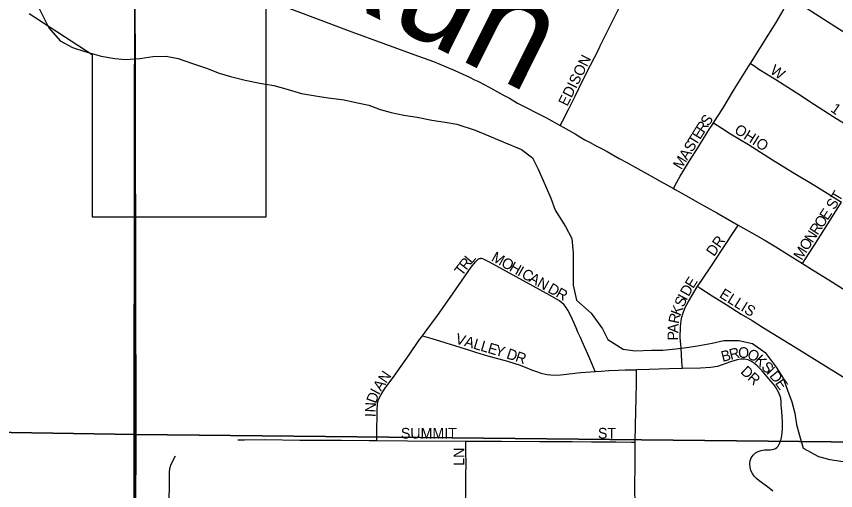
# Model space of a CAD drawing. Extents: x 1874609 to 2204689, y 815661 to 1281160.
# Drawn here: x 2012353 to 2016212, y 1046249 to 1048482 of the extents above; entities that cross this region are included whole.
import ezdxf

# ---------------------------------------------------------------- set-up
doc = ezdxf.new("R2010")
doc.units = 0
for name, color, linetype in [('GM_X_City_Street', 7, 'Continuous'), ('GM_X_City_Street_Text', 7, 'Continuous'), ('GM_X_Corporation', 7, 'Continuous'), ('GM_X_Minor_River', 7, 'Continuous'), ('GM_X_Minor_River_Text', 7, 'Continuous'), ('GM_X_Section', 7, 'Continuous'), ('GM_X_State_Route', 7, 'Continuous'), ('GM_X_Township', 7, 'Continuous')]:
    doc.layers.add(name, color=color, linetype=linetype)

msp = doc.modelspace()

# ---------------------------------------------------------------- linework, layer by layer
at = {"layer": 'GM_X_City_Street'}
for points in [[(2015811.1, 1048260), (2015870.7, 1048355.6), (2015932.6, 1048452.6), (2015964.4, 1048510), (2015971.6, 1048524.4), (2015977.6, 1048539.3), (2015982.3, 1048554.6), (2015986.1, 1048571.6)], [(2015986.1, 1048571.6), (2015992.4, 1048568.6), (2016077.8, 1048518.7), (2016230.2, 1048421.2), (2016352.6, 1048344.8)], [(2014914, 1047967.7), (2014924.9, 1047988.5), (2014955.3, 1048046.6), (2014984.5, 1048105.2), (2015020.1, 1048178.4), (2015057.2, 1048251.2), (2015094.4, 1048324), (2015103.4, 1048342.3), (2015180.9, 1048500.4), (2015196.5, 1048531.8)], [(2015636.4, 1047979.8), (2015680, 1048047.7), (2015731.7, 1048131.9), (2015809.7, 1048257.8), (2015811.1, 1048260)], [(2015811.1, 1048260), (2015826.5, 1048249.8), (2015851, 1048233.5), (2015886.6, 1048211.2), (2015929.6, 1048184.5), (2015969, 1048159.3), (2016038, 1048115.5), (2016112.2, 1048067.2), (2016200.3, 1048010.5), (2016254, 1047977.4), (2016311.9, 1047942), (2016378.6, 1047899.4), (2016410.1, 1047879.7)], [(2015448.1, 1047671.5), (2015464.2, 1047700.6), (2015480.3, 1047729.5), (2015531.9, 1047813.6), (2015557.8, 1047855.3), (2015601.1, 1047923.8), (2015617.8, 1047951.6), (2015627.1, 1047965.3), (2015636.4, 1047979.8)], [(2015636.4, 1047979.8), (2015676, 1047955), (2015717.4, 1047929.1), (2015801, 1047878.1), (2015914, 1047806.8), (2016008.4, 1047748.8), (2016121.6, 1047680), (2016240.5, 1047606.5)], [(2016056, 1047317.5), (2016067, 1047334.7), (2016110.2, 1047402.3), (2016159.6, 1047479.8), (2016240.5, 1047606.5)], [(2015560.9, 1047209.9), (2015623.6, 1047302.9), (2015677.9, 1047384.4), (2015744.9, 1047486), (2015753.2, 1047498.7)], [(2014265.4, 1046977.4), (2014278.1, 1046994.8), (2014336.1, 1047073.6), (2014374.2, 1047126.8), (2014421.1, 1047193.8), (2014495.8, 1047300.2), (2014515.7, 1047325.2), (2014521.5, 1047332.3), (2014526.4, 1047337.6), (2014530.1, 1047340.4), (2014534.5, 1047342.2), (2014539.7, 1047342.2)], [(2015078.9, 1046809.9), (2015063.3, 1046847.4), (2015044.9, 1046891.8), (2015018.2, 1046951), (2015009.8, 1046970.3), (2014998.1, 1046995.1), (2014989.4, 1047014.7), (2014972, 1047054.4), (2014958.2, 1047083.5), (2014950.8, 1047097.6), (2014942.5, 1047110.9), (2014932.6, 1047122.9), (2014921.3, 1047133.6), (2014908.7, 1047143.1), (2014866.9, 1047167.6), (2014738.8, 1047238.7), (2014581.4, 1047324.2), (2014563.1, 1047334.2), (2014549.8, 1047340.4), (2014544.3, 1047341.7), (2014539.7, 1047342.2)], [(2015490.4, 1046822.9), (2015488.2, 1046856.2), (2015484, 1046921.1), (2015481, 1046952.9), (2015480.4, 1046969), (2015481.4, 1047017.5), (2015484.9, 1047049.3), (2015488.2, 1047064.9), (2015492.4, 1047080.3), (2015503.8, 1047110.2), (2015518.3, 1047138.8), (2015559.9, 1047208.4), (2015560.9, 1047209.9)], [(2015560.9, 1047209.9), (2015571.9, 1047202.9), (2015630.5, 1047165.2), (2015696.9, 1047124.3), (2015767.7, 1047080), (2015818.6, 1047049.1), (2015866.8, 1047019), (2015964.8, 1046958.4), (2016020.7, 1046923.7), (2016132.2, 1046854.6), (2016244.2, 1046785.5), (2016385, 1046700), (2016441.2, 1046666.2), (2016466.1, 1046650.2), (2016488.4, 1046635.1), (2016536.8, 1046600.8), (2016599.7, 1046553.8), (2016643.8, 1046520.9), (2016680.8, 1046493), (2016701.2, 1046477.7)], [(2014050.8, 1046484.2), (2014051, 1046501.2), (2014051.5, 1046560.5), (2014051.7, 1046579), (2014052.1, 1046625.7), (2014054.5, 1046658), (2014057.7, 1046673.2), (2014063.3, 1046687.7), (2014070.8, 1046701.7), (2014088.8, 1046728.7), (2014127.1, 1046781.5), (2014202.6, 1046888.3), (2014249.3, 1046955.2), (2014265.4, 1046977.4)], [(2014265.4, 1046977.4), (2014309.6, 1046964.1), (2014325.4, 1046959.4), (2014371.6, 1046945.3), (2014401.7, 1046936.1), (2014416.7, 1046931.3), (2014446.8, 1046922.1), (2014483.3, 1046910.8), (2014516.1, 1046900.5), (2014556.4, 1046888.3), (2014613.6, 1046872.4), (2014655.7, 1046861.2), (2014691.4, 1046850.4), (2014706.1, 1046845.3), (2014720.8, 1046840.1), (2014749.7, 1046829.2), (2014778.6, 1046818.1), (2014808, 1046807.4), (2014823.1, 1046802.3), (2014838.4, 1046797.9), (2014853.9, 1046794.7), (2014869.1, 1046793.1), (2014899.8, 1046792.9), (2014931.4, 1046795.2), (2014995.3, 1046803.5), (2015011.5, 1046804.6), (2015078.9, 1046809.9)], [(2015916.2, 1046245.4), (2015891, 1046266.9), (2015851.2, 1046295), (2015839.1, 1046305.3), (2015828.5, 1046317), (2015819.7, 1046329.9), (2015812.9, 1046344), (2015808.7, 1046358.9), (2015807.4, 1046374.1), (2015809.4, 1046389.1), (2015814.7, 1046403.2), (2015823.2, 1046415.7), (2015834.3, 1046425.8), (2015847.5, 1046433.2), (2015862, 1046437.9), (2015877.5, 1046440), (2015893.7, 1046440.8), (2015904.2, 1046441.3), (2015912.4, 1046442.3), (2015921.1, 1046444.5), (2015928.8, 1046447.5), (2015935.7, 1046452.3), (2015941.4, 1046458.6), (2015946, 1046467.6), (2015949.1, 1046473.7), (2015952.8, 1046483.9), (2015954.9, 1046491.1), (2015958.4, 1046506.5), (2015960.6, 1046523), (2015961.9, 1046539.5), (2015962.3, 1046556.1), (2015961.8, 1046572.5), (2015958, 1046620.7), (2015956.8, 1046635.6), (2015955.8, 1046650.9), (2015955.4, 1046667.3), (2015953.7, 1046684.6), (2015947.6, 1046701.1), (2015940.6, 1046714.6), (2015934.9, 1046725.8), (2015928.1, 1046737.1), (2015919.1, 1046749.4), (2015908.8, 1046762.2), (2015897.8, 1046775.1), (2015865.3, 1046812.3), (2015842, 1046836.1), (2015829.2, 1046847.1), (2015815.1, 1046856.8), (2015799.3, 1046863.9), (2015782.5, 1046867.5), (2015765.3, 1046867.3), (2015748.5, 1046864.5), (2015716.3, 1046855.7), (2015655, 1046833.3), (2015623.4, 1046827.8), (2015574.9, 1046824.4), (2015490.4, 1046822.9)], [(2015078.9, 1046809.9), (2015107, 1046811.5), (2015144.1, 1046813.4), (2015188.2, 1046816.3), (2015220.5, 1046817), (2015274.5, 1046817.7)], [(2015268, 1046477), (2015269.3, 1046556.2), (2015273.2, 1046686.2), (2015274.3, 1046754.4), (2015274.5, 1046817.7)], [(2015490.4, 1046822.9), (2015427.3, 1046821.9), (2015333.2, 1046818.6), (2015274.5, 1046817.7)], [(2013396.1, 1046488), (2013427, 1046488.3), (2013523.7, 1046488.7), (2013687.5, 1046486.5), (2013785.7, 1046486), (2013883.7, 1046485.8), (2014014.7, 1046484.6), (2014050.8, 1046484.2)], [(2014050.8, 1046484.2), (2014195.1, 1046482.6), (2014469.9, 1046481.1)], [(2014467, 1046133.5), (2014468, 1046182.8), (2014470.4, 1046248.3), (2014470.7, 1046330.4), (2014471.3, 1046363.2), (2014470.3, 1046444.9), (2014469.9, 1046481.1)], [(2014469.9, 1046481.1), (2014472.7, 1046481.1), (2014637.7, 1046481.2), (2014817.3, 1046479.8), (2014901.7, 1046480.1), (2014971, 1046479.1), (2015062, 1046478.3), (2015176.3, 1046477.9), (2015251.1, 1046477.2), (2015268, 1046477)], [(2015267, 1046113.2), (2015267.1, 1046181), (2015266.6, 1046262.6), (2015267.1, 1046376.9), (2015267.9, 1046474.8), (2015268, 1046477)], [(2013073.1, 1046143.1), (2013073.4, 1046335.8), (2013076.1, 1046352), (2013080.2, 1046367.8), (2013086.5, 1046383), (2013102.3, 1046411.9)]]:
    msp.add_lwpolyline(points, dxfattribs=at)
at = {"layer": 'GM_X_Corporation'}
msp.add_lwpolyline([(2012412.4, 1048494.5), (2012709.9, 1048301.4), (2012709.8, 1047537.4), (2013530.1, 1047537.4), (2013530.1, 1048534.6)], dxfattribs=at)
at = {"layer": 'GM_X_Minor_River'}
for points in [[(2012453.3, 1048531), (2012506.3, 1048427), (2012559, 1048367.2), (2012617.4, 1048335.5), (2012675.7, 1048315.8), (2012752.1, 1048294.3), (2012816.4, 1048282.8), (2012866.6, 1048279.1), (2012934.7, 1048283.6), (2012994.8, 1048292.1), (2013059, 1048294.6), (2013115.3, 1048283), (2013181.7, 1048259.4), (2013248, 1048237.8), (2013308.4, 1048214.1), (2013360.7, 1048198.5), (2013431, 1048180.9), (2013499.4, 1048167.4), (2013565.6, 1048155.8), (2013621.9, 1048140.2), (2013696.3, 1048118.7), (2013770.7, 1048105.2), (2013820.9, 1048097.5), (2013897.2, 1048088), (2013959.5, 1048074.5), (2014013.7, 1048062.8), (2014066, 1048043.1), (2014118.3, 1048029.5), (2014178.6, 1048015.9), (2014240.8, 1048006.3), (2014309.2, 1047992.8), (2014373.4, 1047983.2), (2014427.7, 1047973.5), (2014514.1, 1047946.1), (2014578.6, 1047918.5), (2014649, 1047888.9), (2014731.5, 1047855.4), (2014784, 1047815.6), (2014810.5, 1047761.6), (2014835, 1047709.6), (2014869.8, 1047625.6), (2014890.4, 1047569.5), (2014939.1, 1047491.6), (2014969.7, 1047435.6)], [(2014969.7, 1047435.6), (2014976.3, 1047367.4)], [(2014976.3, 1047367.4), (2014976, 1047216.3), (2014991.3, 1047144.9), (2015061.2, 1047084.4), (2015113.1, 1047010), (2015139, 1046959.7), (2015211, 1046915.2), (2015267.1, 1046907), (2015345.3, 1046910.6), (2015397.4, 1046910.4), (2015459.6, 1046916.1), (2015509.7, 1046921.9), (2015561.9, 1046929.7), (2015630.1, 1046943.5), (2015686.2, 1046955.3), (2015756.4, 1046954.9), (2015820.5, 1046940.6), (2015880.5, 1046898.2), (2015932.4, 1046829.8), (2015964.2, 1046777.5), (2015986.1, 1046721.2), (2016006, 1046666.9), (2016019.8, 1046612.7), (2016027.6, 1046560.5), (2016041.5, 1046508.3), (2016059.3, 1046448), (2016131.3, 1046409.6), (2016185.4, 1046395.3), (2016247.5, 1046385)]]:
    msp.add_lwpolyline(points, dxfattribs=at)
at = {"layer": 'GM_X_Section'}
for points in [[(2012905.1, 1051801), (2012915.3, 1046513.3), (2007626.4, 1046598.1), (2007622.1, 1051897.9)], [(2019058.5, 1051739.8), (2019020.7, 1046448.2), (2012915.3, 1046513.3), (2012905.1, 1051801)], [(2012915.3, 1046513.3), (2012892.7, 1041156.5), (2007599.8, 1041247.3), (2007626.4, 1046598.1)], [(2019020.7, 1046448.2), (2018988, 1041097.3), (2012892.7, 1041156.5), (2012915.3, 1046513.3)]]:
    msp.add_lwpolyline(points, close=True, dxfattribs=at)
at = {"layer": 'GM_X_State_Route'}
for points in [[(2013581, 1048540.8), (2013703.1, 1048495.1), (2013737, 1048482.5), (2013933.2, 1048409.3), (2014225.4, 1048302.8), (2014317.2, 1048268.7), (2014407.8, 1048231.2), (2014418.4, 1048226.3)], [(2014418.4, 1048226.3), (2014452.4, 1048210.6), (2014486.9, 1048195.5), (2014511.3, 1048183.6), (2014525.8, 1048176.4), (2014559, 1048159), (2014594.4, 1048140.1), (2014619.9, 1048126.8), (2014647.6, 1048110.2), (2014675.3, 1048095.8), (2014714.1, 1048073.6), (2014847.2, 1048004.9), (2014914, 1047967.7), (2014956.9, 1047943.9), (2014984.6, 1047928.4), (2015007.8, 1047914), (2015031.1, 1047900.7), (2015055.5, 1047887.4), (2015081, 1047874.1), (2015108.7, 1047859.6), (2015135.3, 1047845.2), (2015162.8, 1047829.6), (2015191.9, 1047813.1), (2015228.4, 1047793.1), (2015267.2, 1047771), (2015323.8, 1047739.9), (2015385.8, 1047705.5), (2015448.1, 1047671.5), (2015456.8, 1047666.8), (2015497.8, 1047643.5), (2015562.1, 1047606.9), (2015651.8, 1047555.9), (2015722.8, 1047516), (2015753.2, 1047498.7), (2015818.1, 1047461.7), (2015874.7, 1047430), (2015930.4, 1047396), (2015985.8, 1047361.3), (2016056, 1047317.5), (2016110.7, 1047283.3), (2016179.7, 1047241.1), (2016262.2, 1047189)]]:
    msp.add_lwpolyline(points, dxfattribs=at)
at = {"layer": 'GM_X_Township'}
for points in [[(2012924.9, 1056002.2), (2012935.3, 1053679.3), (2012914.5, 1051827.7), (2012910.2, 1048822.6), (2012903.7, 1044302.1), (2012899.1, 1041173.4), (2012896.1, 1039044.8), (2012861.2, 1035880.2), (2012864.4, 1032937.1), (2012859.2, 1032479.4), (2012845.9, 1030538.4), (2012837.6, 1027645.9), (2012830.6, 1025241.9), (2010175.8, 1025275.6)], [(2037504.4, 1025002.2), (2030477.9, 1025070.5), (2023338.3, 1025139.8), (2019554.9, 1025176.6), (2018880.2, 1025183.1), (2014559, 1025225.1), (2013359, 1025236.7), (2012830.6, 1025241.9), (2012837.6, 1027645.9), (2012845.9, 1030538.4), (2012859.2, 1032479.4), (2012864.4, 1032937.1), (2012861.2, 1035880.2), (2012896.1, 1039044.8), (2012899.1, 1041173.4), (2012903.7, 1044302.1), (2012910.2, 1048822.6), (2012914.5, 1051827.7), (2012935.3, 1053679.3), (2012924.9, 1056002.2)]]:
    msp.add_lwpolyline(points, dxfattribs=at)

# ---------------------------------------------------------------- texts
at = {"layer": 'GM_X_City_Street_Text'}
for s, rotation, p in [('EDISON', 63.4349, (2014947.5, 1048055.1)), ('W', 326.0162, (2015899.3, 1048216.4)), ('1', 324.8724, (2016184.6, 1048036.6)), ('S', 55.6659, (2015612.8, 1047961.3)), ('R', 57.2867, (2015591.7, 1047928.3)), ('E', 58.0989, (2015573.2, 1047898.6)), ('OHIO', 327.6586, (2015731, 1047935.6)), ('T', 58.0989, (2015554.6, 1047868.7)), ('S', 58.1095, (2015536, 1047838.9)), ('M', 58.0834, (2015484.8, 1047756.7)), ('A', 58.0908, (2015512.7, 1047801.5)), ('ST', 59.0277, (2016206.3, 1047567.4)), ('E', 56.3071, (2016173.4, 1047518.1)), ('O', 56.3099, (2016149, 1047481.5)), ('N', 56.6252, (2016102.9, 1047411.8)), ('R', 56.3234, (2016127.1, 1047448.5)), ('DR', 54.7814, (2015639, 1047347.8)), ('O', 58.1104, (2016079.8, 1047374.8)), ('M', 58.5333, (2016052.3, 1047329.8)), ('M', 330.8357, (2014586.5, 1047333.1)), ('R', 52.2388, (2014472.9, 1047283.5)), ('L', 49.6032, (2014496.8, 1047314.3)), ('O', 330.8244, (2014632.7, 1047307.4)), ('H', 330.8267, (2014671.1, 1047285.9)), ('T', 52.2448, (2014451.4, 1047255.6)), ('I', 330.8137, (2014709.5, 1047264.5)), ('C', 330.8422, (2014728.7, 1047253.8)), ('A', 330.8244, (2014763.3, 1047234.5)), ('N', 330.8267, (2014801.7, 1047213)), ('E', 57.9541, (2015540.8, 1047197.1)), ('D', 330.8244, (2014851.7, 1047185.1)), ('R', 331.0174, (2014890.2, 1047163.6)), ('D', 60.6482, (2015519.6, 1047159.3)), ('I', 62.4573, (2015509.6, 1047140.2)), ('ELLIS', 327.9952, (2015660.5, 1047161.3)), ('S', 65.8794, (2015495.6, 1047108.8)), ('K', 68.5639, (2015479.7, 1047068.4)), ('R', 78.0613, (2015472.2, 1047031.7)), ('A', 87.3111, (2015470.4, 1046989.9)), ('V', 343.7634, (2014417.4, 1046942.3)), ('A', 343.7882, (2014459.7, 1046930)), ('P', 89.6175, (2015470.1, 1046955.2)), ('L', 343.7769, (2014501.9, 1046917.7)), ('L', 343.7612, (2014535.7, 1046907.9)), ('E', 343.7845, (2014569.5, 1046898)), ('Y', 343.7153, (2014603.3, 1046888.2)), ('D', 341.9797, (2014657.8, 1046872.1)), ('R', 341.5651, (2014699.5, 1046858.6)), ('B', 14.3838, (2015679.4, 1046854.4)), ('R', 14.3765, (2015717.8, 1046864.2)), ('O', 0.4809, (2015753, 1046873.6)), ('O', 333.3665, (2015790.9, 1046875.4)), ('K', 315.6337, (2015826.9, 1046858)), ('D', 316.5766, (2015760.7, 1046804.7)), ('S', 314.5942, (2015858.2, 1046827.4)), ('I', 314.5674, (2015882.9, 1046802.4)), ('N', 56.2311, (2014094.8, 1046750.6)), ('R', 317.656, (2015793.4, 1046773.8)), ('D', 309.5201, (2015897.6, 1046787.6)), ('E', 304.8645, (2015924.9, 1046754.5)), ('A', 56.6252, (2014070.7, 1046713.9)), ('D', 70.1551, (2014046.6, 1046656)), ('I', 61.3826, (2014060.7, 1046695.5)), ('N', 87.3111, (2014045.3, 1046615.9)), ('I', 88.4696, (2014044.7, 1046594.2)), ('SUMMIT', 0, (2014164, 1046493.9)), ('ST', 0, (2015092.4, 1046493.9)), ('LN', 90, (2014462.5, 1046365.7))]:
    msp.add_text(s, height=50, rotation=rotation, dxfattribs=at).set_placement(p)
at = {"layer": 'GM_X_Minor_River_Text'}
msp.add_text('Run', height=500.16, rotation=333.4574, dxfattribs=at).set_placement((2013662.6, 1048666.3))

doc.saveas('drawing.dxf')
